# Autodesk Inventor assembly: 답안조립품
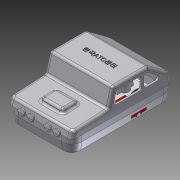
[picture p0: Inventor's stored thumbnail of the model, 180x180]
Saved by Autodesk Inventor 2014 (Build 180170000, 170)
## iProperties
Created: 2015-06
Part Number: 답안조립품
Document SubType Name: Assembly
Designer: Administrator
Author: Administrator
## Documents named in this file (6)
- C:\Documents and Settings\Administrator\바탕 화면\450508V1029\답안조립품.iam
- C:\Documents and Settings\Administrator\바탕 화면\450508V1029\본체.ipt
- C:\Documents and Settings\Administrator\바탕 화면\450508V1029\커버.ipt
- C:\Documents and Settings\Administrator\바탕 화면\450508V1029\M4x10.ipt
- C:\Documents and Settings\Administrator\바탕 화면\450508V1029\바퀴.ipt
- C:\Documents and Settings\Administrator\바탕 화면\450508V1029\바퀴고정부.ipt
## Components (4 placed, 1 different names)
1. M4x10:1
2. M4x10:2
3. M4x10:3
4. M4x10:4
